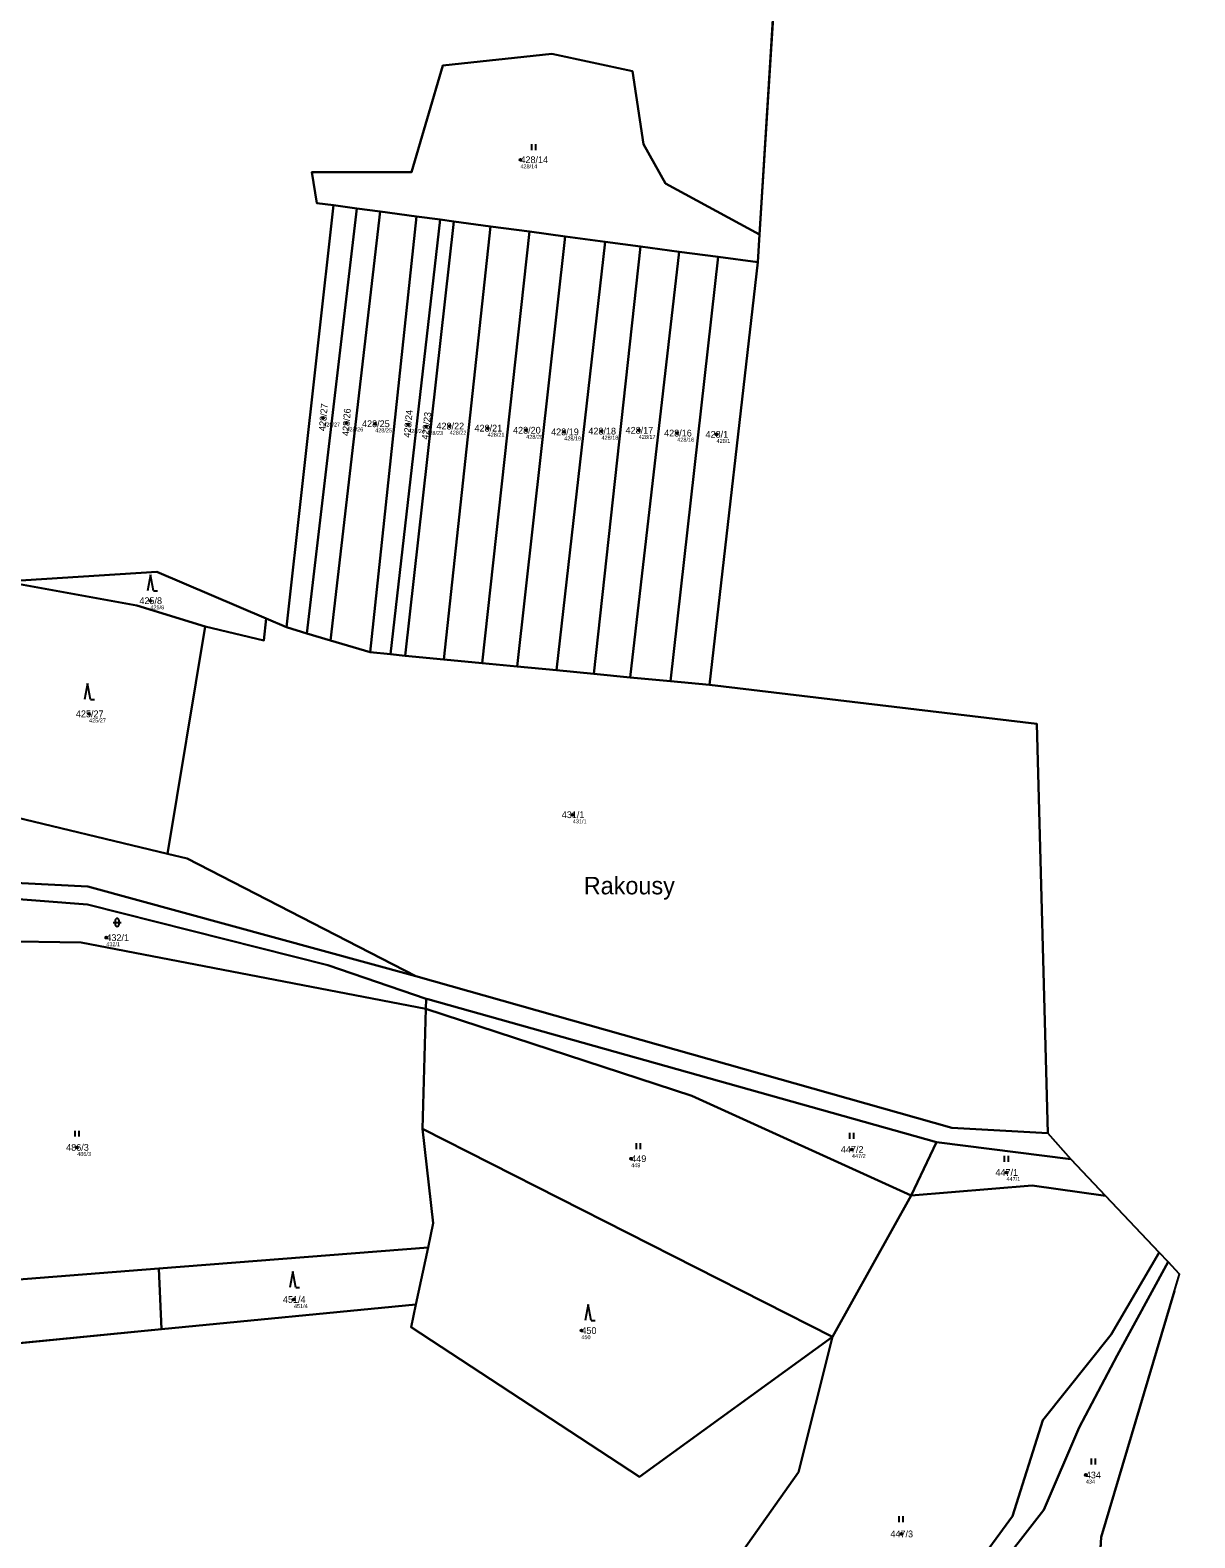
# Model space of a CAD drawing. Extents: x -767985 to -763816, y -1059600 to -1057360.
# Drawn here: x -764767.3 to -764474.7, y -1058127.9 to -1057748.9 of the extents above; entities that cross this region are included whole.
import ezdxf

# ---------------------------------------------------------------- set-up
doc = ezdxf.new("R2010")
doc.units = 0
for name, color, linetype in [('Definiční body', 7, 'Continuous'), ('Hranice parcel', 7, 'Continuous'), ('Parcelní čísla', 7, 'Continuous'), ('Polygon ku', 7, 'Continuous'), ('Polygon parcely', 7, 'Continuous'), ('Pop  PČ popisy', 7, 'Continuous'), ('Značky kultur', 7, 'Continuous')]:
    doc.layers.add(name, color=color, linetype=linetype)

msp = doc.modelspace()

# ---------------------------------------------------------------- linework, layer by layer
at = {"layer": 'Definiční body'}
for centre in [(-764644.16, -1057781.51994), (-764693.7, -1057846.41994), (-764687.88, -1057847.64994), (-764680.65, -1057847.87994), (-764672.38, -1057848.05994), (-764667.81, -1057848.55994), (-764661.95, -1057848.46994), (-764652.39, -1057848.98994), (-764642.71, -1057849.50994), (-764633.14, -1057849.91994), (-764623.79, -1057849.72994), (-764614.43, -1057849.51994), (-764604.75, -1057850.22994), (-764594.87, -1057850.53994), (-764737.12, -1057892.35994), (-764752.54, -1057920.79994), (-764631, -1057946.14994), (-764748.2, -1057977.04994), (-764755.52, -1058029.76994), (-764560.87, -1058030.28994), (-764616.32, -1058032.60994), (-764522.04, -1058036.07994), (-764701.06, -1058068.00994), (-764628.84, -1058075.81994), (-764502.1, -1058112.11994), (-764548.43, -1058126.92994)]:
    msp.add_circle(centre, 0.25, dxfattribs=at)
at = {"layer": 'Hranice parcel'}
for p, q in [((-764578.12, -1057704.17), (-764584.05, -1057800.31)), ((-764702.89, -1057899.01), (-764691.14, -1057792.96)), ((-764685.22, -1057793.76), (-764697.79, -1057900.56)), ((-764679.4, -1057794.54), (-764691.85, -1057902.37)), ((-764691.14, -1057792.96), (-764685.22, -1057793.76)), ((-764685.22, -1057793.76), (-764679.4, -1057794.54)), ((-764679.4, -1057794.54), (-764670.24, -1057795.77)), ((-764670.24, -1057795.77), (-764681.95, -1057905.33)), ((-764664.3, -1057796.57), (-764676.81, -1057905.83)), ((-764660.87, -1057797.03), (-764673.09, -1057906.19)), ((-764670.24, -1057795.77), (-764664.3, -1057796.57)), ((-764664.3, -1057796.57), (-764660.87, -1057797.03)), ((-764651.7, -1057798.26), (-764663.4, -1057907.12)), ((-764660.87, -1057797.03), (-764651.7, -1057798.26)), ((-764651.7, -1057798.26), (-764641.84, -1057799.59)), ((-764641.84, -1057799.59), (-764653.8, -1057908.04)), ((-764632.94, -1057800.79), (-764644.97, -1057908.89)), ((-764641.84, -1057799.59), (-764632.94, -1057800.79)), ((-764622.87, -1057802.14), (-764635.12, -1057909.84)), ((-764632.94, -1057800.79), (-764622.87, -1057802.14)), ((-764622.87, -1057802.14), (-764614.01, -1057803.33)), ((-764584.05, -1057800.31), (-764584.48, -1057807.3)), ((-764614.01, -1057803.33), (-764625.75, -1057910.74)), ((-764604.26, -1057804.64), (-764616.56, -1057911.63)), ((-764614.01, -1057803.33), (-764604.26, -1057804.64)), ((-764594.47, -1057805.96), (-764606.47, -1057912.6)), ((-764604.26, -1057804.64), (-764594.47, -1057805.96)), ((-764584.48, -1057807.3), (-764594.47, -1057805.96)), ((-764584.48, -1057807.3), (-764596.65, -1057913.54)), ((-764708.04, -1057896.82), (-764702.89, -1057899.01)), ((-764723.34, -1057898.88), (-764732.83, -1057955.96)), ((-764697.79, -1057900.56), (-764702.89, -1057899.01)), ((-764691.85, -1057902.37), (-764697.79, -1057900.56)), ((-764681.95, -1057905.33), (-764691.85, -1057902.37)), ((-764676.81, -1057905.83), (-764681.95, -1057905.33)), ((-764673.09, -1057906.19), (-764676.81, -1057905.83)), ((-764663.4, -1057907.12), (-764673.09, -1057906.19)), ((-764653.8, -1057908.04), (-764663.4, -1057907.12)), ((-764644.97, -1057908.89), (-764653.8, -1057908.04)), ((-764635.12, -1057909.84), (-764644.97, -1057908.89)), ((-764625.75, -1057910.74), (-764635.12, -1057909.84)), ((-764616.56, -1057911.63), (-764625.75, -1057910.74)), ((-764606.47, -1057912.6), (-764616.56, -1057911.63)), ((-764606.47, -1057912.6), (-764596.65, -1057913.54)), ((-764732.83, -1057955.96), (-764775.4, -1057945.74)), ((-764667.92, -1057994.92), (-764667.83, -1057992.4)), ((-764667.92, -1057994.92), (-764668.76, -1058025.15)), ((-764668.76, -1058025.15), (-764565.76, -1058077.36)), ((-764511.61, -1058026.16), (-764505.87, -1058032.76)), ((-764539.65, -1058028.5), (-764546, -1058041.83)), ((-764505.87, -1058032.76), (-764539.65, -1058028.5)), ((-764505.87, -1058032.76), (-764497.19, -1058041.93)), ((-764565.76, -1058077.36), (-764546, -1058041.83)), ((-764497.19, -1058041.93), (-764483.69, -1058056.17)), ((-764667.35, -1058054.9), (-764735.02, -1058060.23)), ((-764667.35, -1058054.9), (-764670.42, -1058069.3)), ((-764481.44, -1058058.55), (-764483.69, -1058056.17)), ((-764735.02, -1058060.23), (-764846.86, -1058069.03)), ((-764734.36, -1058075.5), (-764735.02, -1058060.23)), ((-764479.78, -1058065.86), (-764498.27, -1058127.76)), ((-764734.36, -1058075.5), (-764670.42, -1058069.3)), ((-764797.69, -1058081.64), (-764734.36, -1058075.5)), ((-764498.27, -1058127.76), (-764499.24, -1058144.19))]:
    msp.add_line(p, q, dxfattribs=at)
for points in [[(-764691.14, -1057792.96), (-764695.27, -1057792.41), (-764696.56, -1057784.68), (-764671.54, -1057784.6), (-764663.65, -1057757.85), (-764636.23, -1057754.86), (-764616.02, -1057759.27), (-764613.2, -1057777.63), (-764607.74, -1057787.49), (-764584.05, -1057800.31)], [(-764773.72, -1057887.53), (-764735.5, -1057885.13), (-764708.04, -1057896.82)], [(-764773.72, -1057887.53), (-764740.53, -1057893.58), (-764723.34, -1057898.88)], [(-764723.34, -1057898.88), (-764708.6, -1057902.39), (-764708.04, -1057896.82)], [(-764596.65, -1057913.54), (-764514.41, -1057923.33), (-764511.61, -1058026.16)], [(-764732.83, -1057955.96), (-764727.9, -1057957.13), (-764670.44, -1057986.77)], [(-764867.2, -1057970.69), (-764810.99, -1057961.28), (-764752.85, -1057964.23), (-764670.44, -1057986.77)], [(-764667.83, -1057992.4), (-764692.55, -1057983.97), (-764752.96, -1057968.74), (-764775.73, -1057966.92)], [(-764775.99, -1057977.9), (-764754.5, -1057978.28), (-764667.92, -1057994.92)], [(-764670.44, -1057986.77), (-764535.77, -1058024.86), (-764511.61, -1058026.16)], [(-764539.65, -1058028.5), (-764667.4, -1057992.55), (-764667.83, -1057992.4)], [(-764546, -1058041.83), (-764601.09, -1058016.78), (-764667.92, -1057994.92)], [(-764668.76, -1058025.15), (-764666.06, -1058048.83), (-764667.35, -1058054.9)], [(-764546, -1058041.83), (-764515.56, -1058039.39), (-764497.19, -1058041.93)], [(-764483.69, -1058056.17), (-764495.72, -1058076.83), (-764512.87, -1058098.33), (-764520.48, -1058122.51), (-764535.32, -1058142.75), (-764540.71, -1058158.07), (-764556.13, -1058229.11)], [(-764499.24, -1058144.19), (-764525.84, -1058137.89), (-764512.69, -1058120.87), (-764503.77, -1058100.18), (-764494.21, -1058082.06), (-764481.44, -1058058.55)], [(-764479.78, -1058065.86), (-764478.52, -1058061.63), (-764481.44, -1058058.55)], [(-764670.42, -1058069.3), (-764671.64, -1058075), (-764614.26, -1058112.61), (-764565.76, -1058077.36)], [(-764615.43, -1058164.63), (-764604.16, -1058153.69), (-764574.29, -1058111.37), (-764565.76, -1058077.36)]]:
    msp.add_lwpolyline(points, dxfattribs=at)
at = {"layer": 'Polygon ku'}
msp.add_lwpolyline([(-764406.14, -1058356.86), (-764487.98, -1058370.5), (-764486.4, -1058358), (-764485.87, -1058342.5), (-764501.57, -1058261.88), (-764501.99, -1058233.31), (-764502.44, -1058203.21), (-764502.49, -1058199.51), (-764499.56, -1058149.61), (-764499.24, -1058144.19), (-764498.27, -1058127.76), (-764479.78, -1058065.86), (-764478.52, -1058061.63), (-764481.44, -1058058.55), (-764483.69, -1058056.17), (-764497.19, -1058041.93), (-764505.87, -1058032.76), (-764511.61, -1058026.16), (-764514.41, -1057923.33), (-764596.65, -1057913.54), (-764584.48, -1057807.3), (-764584.05, -1057800.31), (-764578.12, -1057704.17)], dxfattribs=at)
at = {"layer": 'Polygon parcely'}
for points in [[(-764773.72, -1057887.53), (-764735.5, -1057885.13), (-764708.04, -1057896.82), (-764702.89, -1057899.01), (-764691.14, -1057792.96), (-764695.27, -1057792.41), (-764696.56, -1057784.68), (-764671.54, -1057784.6), (-764663.65, -1057757.85), (-764636.23, -1057754.86), (-764616.02, -1057759.27), (-764613.2, -1057777.63), (-764607.74, -1057787.49), (-764584.05, -1057800.31), (-764578.12, -1057704.17)], [(-764775.73, -1057966.92), (-764752.96, -1057968.74), (-764692.55, -1057983.97), (-764667.83, -1057992.4), (-764667.4, -1057992.55), (-764539.65, -1058028.5), (-764505.87, -1058032.76), (-764511.61, -1058026.16), (-764535.77, -1058024.86), (-764670.44, -1057986.77), (-764752.85, -1057964.23), (-764810.99, -1057961.28)], [(-764773.89, -1058326.01), (-764738.41, -1058322.75), (-764710.58, -1058315.22), (-764677.8, -1058302.86), (-764662.17, -1058302.69), (-764664.07, -1058311.08), (-764651.78, -1058300.96), (-764643.66, -1058278.56), (-764629.33, -1058256.93), (-764623.43, -1058248.02), (-764639.81, -1058211.84), (-764639.52, -1058210.13), (-764636.12, -1058196.74), (-764632.07, -1058180.77), (-764615.43, -1058164.63), (-764604.16, -1058153.69), (-764574.29, -1058111.37), (-764565.76, -1058077.36), (-764614.26, -1058112.61), (-764671.64, -1058075), (-764670.42, -1058069.3), (-764734.36, -1058075.5), (-764797.69, -1058081.64)]]:
    msp.add_lwpolyline(points, dxfattribs=at)
for points in [[(-764679.4, -1057794.54), (-764670.24, -1057795.77), (-764664.3, -1057796.57), (-764660.87, -1057797.03), (-764651.7, -1057798.26), (-764641.84, -1057799.59), (-764632.94, -1057800.79), (-764622.87, -1057802.14), (-764614.01, -1057803.33), (-764604.26, -1057804.64), (-764594.47, -1057805.96), (-764584.48, -1057807.3), (-764584.05, -1057800.31), (-764607.74, -1057787.49), (-764613.2, -1057777.63), (-764616.02, -1057759.27), (-764636.23, -1057754.86), (-764663.65, -1057757.85), (-764671.54, -1057784.6), (-764696.56, -1057784.68), (-764695.27, -1057792.41), (-764691.14, -1057792.96), (-764685.22, -1057793.76)], [(-764691.14, -1057792.96), (-764702.89, -1057899.01), (-764697.79, -1057900.56), (-764685.22, -1057793.76)], [(-764697.79, -1057900.56), (-764691.85, -1057902.37), (-764679.4, -1057794.54), (-764685.22, -1057793.76)], [(-764691.85, -1057902.37), (-764681.95, -1057905.33), (-764670.24, -1057795.77), (-764679.4, -1057794.54)], [(-764681.95, -1057905.33), (-764676.81, -1057905.83), (-764664.3, -1057796.57), (-764670.24, -1057795.77)], [(-764676.81, -1057905.83), (-764673.09, -1057906.19), (-764660.87, -1057797.03), (-764664.3, -1057796.57)], [(-764673.09, -1057906.19), (-764663.4, -1057907.12), (-764651.7, -1057798.26), (-764660.87, -1057797.03)], [(-764663.4, -1057907.12), (-764653.8, -1057908.04), (-764641.84, -1057799.59), (-764651.7, -1057798.26)], [(-764653.8, -1057908.04), (-764644.97, -1057908.89), (-764632.94, -1057800.79), (-764641.84, -1057799.59)], [(-764644.97, -1057908.89), (-764635.12, -1057909.84), (-764622.87, -1057802.14), (-764632.94, -1057800.79)], [(-764635.12, -1057909.84), (-764625.75, -1057910.74), (-764614.01, -1057803.33), (-764622.87, -1057802.14)], [(-764625.75, -1057910.74), (-764616.56, -1057911.63), (-764604.26, -1057804.64), (-764614.01, -1057803.33)], [(-764616.56, -1057911.63), (-764606.47, -1057912.6), (-764594.47, -1057805.96), (-764604.26, -1057804.64)], [(-764596.65, -1057913.54), (-764584.48, -1057807.3), (-764594.47, -1057805.96), (-764606.47, -1057912.6)], [(-764740.53, -1057893.58), (-764723.34, -1057898.88), (-764708.6, -1057902.39), (-764708.04, -1057896.82), (-764735.5, -1057885.13), (-764773.72, -1057887.53)], [(-764723.34, -1057898.88), (-764740.53, -1057893.58), (-764773.72, -1057887.53), (-764775.4, -1057945.74), (-764732.83, -1057955.96)], [(-764708.04, -1057896.82), (-764708.6, -1057902.39), (-764723.34, -1057898.88), (-764732.83, -1057955.96), (-764727.9, -1057957.13), (-764670.44, -1057986.77), (-764535.77, -1058024.86), (-764511.61, -1058026.16), (-764514.41, -1057923.33), (-764596.65, -1057913.54), (-764606.47, -1057912.6), (-764616.56, -1057911.63), (-764625.75, -1057910.74), (-764635.12, -1057909.84), (-764644.97, -1057908.89), (-764653.8, -1057908.04), (-764663.4, -1057907.12), (-764673.09, -1057906.19), (-764676.81, -1057905.83), (-764681.95, -1057905.33), (-764691.85, -1057902.37), (-764697.79, -1057900.56), (-764702.89, -1057899.01)], [(-764810.99, -1057961.28), (-764752.85, -1057964.23), (-764670.44, -1057986.77), (-764727.9, -1057957.13), (-764732.83, -1057955.96), (-764775.4, -1057945.74), (-764830.95, -1057939.9), (-764839.22, -1057950.88), (-764840.4, -1057965.52), (-764864.88, -1057954.96), (-764866.61, -1057966.77), (-764867.2, -1057970.69)], [(-764752.96, -1057968.74), (-764775.73, -1057966.92), (-764775.99, -1057977.9), (-764754.5, -1057978.28), (-764667.92, -1057994.92), (-764667.83, -1057992.4), (-764692.55, -1057983.97)], [(-764846.86, -1058069.03), (-764735.02, -1058060.23), (-764667.35, -1058054.9), (-764666.06, -1058048.83), (-764668.76, -1058025.15), (-764667.92, -1057994.92), (-764754.5, -1057978.28), (-764775.99, -1057977.9), (-764816.05, -1057977.34), (-764843.12, -1057982.67)], [(-764667.83, -1057992.4), (-764667.92, -1057994.92), (-764601.09, -1058016.78), (-764546, -1058041.83), (-764539.65, -1058028.5), (-764667.4, -1057992.55)], [(-764668.76, -1058025.15), (-764565.76, -1058077.36), (-764546, -1058041.83), (-764601.09, -1058016.78), (-764667.92, -1057994.92)], [(-764667.35, -1058054.9), (-764670.42, -1058069.3), (-764671.64, -1058075), (-764614.26, -1058112.61), (-764565.76, -1058077.36), (-764668.76, -1058025.15), (-764666.06, -1058048.83)], [(-764546, -1058041.83), (-764515.56, -1058039.39), (-764497.19, -1058041.93), (-764505.87, -1058032.76), (-764539.65, -1058028.5)], [(-764636.12, -1058196.74), (-764639.52, -1058210.13), (-764633.15, -1058211.67), (-764629.64, -1058212.47), (-764559.35, -1058228.38), (-764556.13, -1058229.11), (-764540.71, -1058158.07), (-764535.32, -1058142.75), (-764520.48, -1058122.51), (-764512.87, -1058098.33), (-764495.72, -1058076.83), (-764483.69, -1058056.17), (-764497.19, -1058041.93), (-764515.56, -1058039.39), (-764546, -1058041.83), (-764565.76, -1058077.36), (-764574.29, -1058111.37), (-764604.16, -1058153.69), (-764615.43, -1058164.63), (-764613.39, -1058202.7)], [(-764670.42, -1058069.3), (-764667.35, -1058054.9), (-764735.02, -1058060.23), (-764734.36, -1058075.5)], [(-764481.44, -1058058.55), (-764483.69, -1058056.17), (-764495.72, -1058076.83), (-764512.87, -1058098.33), (-764520.48, -1058122.51), (-764535.32, -1058142.75), (-764540.71, -1058158.07), (-764556.13, -1058229.11), (-764501.99, -1058233.31), (-764550.12, -1058222.69), (-764541.57, -1058205.49), (-764541.75, -1058183.05), (-764530.44, -1058143.68), (-764499.56, -1058149.61), (-764499.24, -1058144.19), (-764525.84, -1058137.89), (-764512.69, -1058120.87), (-764503.77, -1058100.18), (-764494.21, -1058082.06)], [(-764846.86, -1058069.03), (-764799.14, -1058075.76), (-764797.69, -1058081.64), (-764734.36, -1058075.5), (-764735.02, -1058060.23)], [(-764479.78, -1058065.86), (-764478.52, -1058061.63), (-764481.44, -1058058.55), (-764494.21, -1058082.06), (-764503.77, -1058100.18), (-764512.69, -1058120.87), (-764525.84, -1058137.89), (-764499.24, -1058144.19), (-764498.27, -1058127.76)]]:
    msp.add_lwpolyline(points, close=True, dxfattribs=at)
at = {"layer": 'Značky kultur'}
for p, q in [((-764641.271, -1057779.11), (-764641.271, -1057777.61)), ((-764640.27, -1057779.11), (-764640.27, -1057777.61)), ((-764737.12, -1057885.85), (-764737.87, -1057889.85)), ((-764736.37, -1057889.85), (-764737.12, -1057885.85)), ((-764736.37, -1057889.85), (-764735.374, -1057889.85)), ((-764752.92, -1057913.15), (-764753.67, -1057917.15)), ((-764752.17, -1057917.15), (-764752.92, -1057913.15)), ((-764752.17, -1057917.15), (-764751.174, -1057917.15)), ((-764746.491, -1057973.231), (-764744.489, -1057973.231)), ((-764745.991, -1057972.731), (-764745.991, -1057973.732)), ((-764744.989, -1057973.732), (-764744.989, -1057972.731)), ((-764756.031, -1058027.07), (-764756.031, -1058025.57)), ((-764755.03, -1058027.07), (-764755.03, -1058025.57)), ((-764561.381, -1058027.59), (-764561.381, -1058026.09)), ((-764560.38, -1058027.59), (-764560.38, -1058026.09)), ((-764614.971, -1058030.21), (-764614.971, -1058028.71)), ((-764613.97, -1058030.21), (-764613.97, -1058028.71)), ((-764522.551, -1058033.38), (-764522.551, -1058031.88)), ((-764521.55, -1058033.38), (-764521.55, -1058031.88)), ((-764701.37, -1058061.01), (-764702.12, -1058065.01)), ((-764700.62, -1058065.01), (-764701.37, -1058061.01)), ((-764700.62, -1058065.01), (-764699.624, -1058065.01)), ((-764627.16, -1058069.29), (-764627.91, -1058073.29)), ((-764626.41, -1058073.29), (-764627.16, -1058069.29)), ((-764626.41, -1058073.29), (-764625.414, -1058073.29)), ((-764500.681, -1058109.48), (-764500.681, -1058107.98)), ((-764499.68, -1058109.48), (-764499.68, -1058107.98)), ((-764548.981, -1058123.99), (-764548.981, -1058122.49)), ((-764547.98, -1058123.99), (-764547.98, -1058122.49))]:
    msp.add_line(p, q, dxfattribs=at)
for centre, start, end in [((-764745.49, -1057972.7309), 0, 180), ((-764745.49, -1057973.7309), 180, 359.9878861)]:
    msp.add_arc(centre, 0.5, start, end, dxfattribs=at)

# ---------------------------------------------------------------- texts
at = {"layer": 'Definiční body'}
for s, p in [('428/14', (-764644.16, -1057783.676)), ('428/27', (-764693.7, -1057848.576)), ('428/26', (-764687.88, -1057849.806)), ('428/25', (-764680.65, -1057850.036)), ('428/24', (-764672.38, -1057850.216)), ('428/23', (-764667.81, -1057850.716)), ('428/22', (-764661.95, -1057850.626)), ('428/21', (-764652.39, -1057851.146)), ('428/20', (-764642.71, -1057851.666)), ('428/19', (-764633.14, -1057852.076)), ('428/18', (-764623.79, -1057851.886)), ('428/17', (-764614.43, -1057851.676)), ('428/16', (-764604.75, -1057852.386)), ('428/1', (-764594.87, -1057852.696)), ('425/8', (-764737.12, -1057894.516)), ('425/27', (-764752.54, -1057922.956)), ('431/1', (-764631, -1057948.306)), ('432/1', (-764748.2, -1057979.206)), ('486/3', (-764755.52, -1058031.926)), ('449', (-764616.32, -1058034.766)), ('447/2', (-764560.87, -1058032.446)), ('447/1', (-764522.04, -1058038.236)), ('451/4', (-764701.06, -1058070.166)), ('450', (-764628.84, -1058077.976)), ('434', (-764502.1, -1058114.276))]:
    msp.add_text(s, height=0.999996, dxfattribs=at).set_placement(p)
at = {"layer": 'Parcelní čísla'}
for s, p in [('428/14', (-764644.16, -1057782.37)), ('428/25', (-764683.955, -1057848.73)), ('428/22', (-764665.255, -1057849.32)), ('428/21', (-764655.695, -1057849.84)), ('428/20', (-764646.015, -1057850.36)), ('428/19', (-764636.445, -1057850.77)), ('428/18', (-764627.095, -1057850.58)), ('428/17', (-764617.735, -1057850.37)), ('428/16', (-764608.055, -1057851.08)), ('428/1', (-764597.643, -1057851.39)), ('425/8', (-764739.893, -1057893.21)), ('425/27', (-764755.845, -1057921.65)), ('431/1', (-764633.773, -1057947)), ('432/1', (-764748.2, -1057977.9)), ('486/3', (-764758.293, -1058030.62)), ('447/2', (-764563.643, -1058031.14)), ('449', (-764616.32, -1058033.46)), ('447/1', (-764524.813, -1058036.93)), ('451/4', (-764703.833, -1058068.86)), ('450', (-764628.84, -1058076.67)), ('434', (-764502.1, -1058112.97)), ('447/3', (-764551.203, -1058127.78))]:
    msp.add_text(s, height=1.699998, dxfattribs=at).set_placement(p)
for s, rotation, p in [('428/27', 85, (-764693.141, -1057849.787)), ('428/26', 86, (-764687.262, -1057851.006)), ('428/24', 85, (-764671.821, -1057851.427)), ('428/23', 84, (-764667.31, -1057851.936))]:
    msp.add_text(s, height=1.699998, rotation=rotation, dxfattribs=at).set_placement(p)
at = {"layer": 'Pop  PČ popisy'}
msp.add_text('Rakousy', height=4.399998, dxfattribs=at).set_placement((-764628.25, -1057966.169))

doc.saveas('drawing.dxf')
